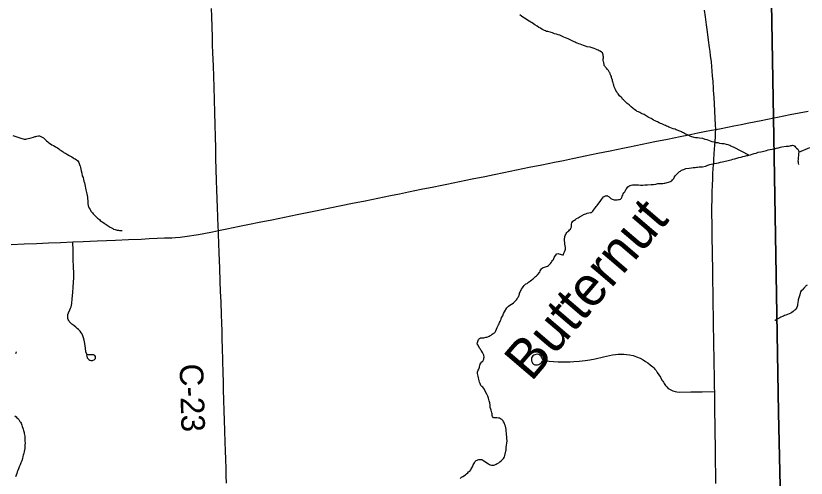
# Model space of a CAD drawing. Extents: x 103424 to 290657, y 38711 to 110967.
# Drawn here: x 139139 to 149253, y 78949 to 84863 of the extents above; entities that cross this region are included whole.
import ezdxf

# ---------------------------------------------------------------- set-up
doc = ezdxf.new("R2010")
doc.units = 0
for name, color, linetype in [('GM_X_Corporation', 7, 'Continuous'), ('GM_X_County_Road', 7, 'Continuous'), ('GM_X_County_Road_Text', 7, 'Continuous'), ('GM_X_Minor_River', 7, 'Continuous'), ('GM_X_Minor_River_Text', 7, 'Continuous'), ('GM_X_State_Route', 7, 'Continuous'), ('GM_X_Township_Road', 7, 'Continuous'), ('GM_X_US_Route', 7, 'Continuous'), ('SC_Scratch1', 7, 'Continuous')]:
    doc.layers.add(name, color=color, linetype=linetype)

msp = doc.modelspace()

# ---------------------------------------------------------------- linework, layer by layer
at = {"layer": 'GM_X_Corporation'}
for points in [[(151578, 71708), (149074, 71652), (149050, 72896), (149034, 73733), (149034, 73737), (149016, 74683), (148899, 79790), (148833, 83560), (148595, 97227), (148594, 97295), (158050, 97608)], [(148595, 97227), (148833, 83560), (148899, 79790), (149016, 74683), (149034, 73737), (149034, 73733), (149050, 72896), (149074, 71652), (148227, 71628), (148226, 71628), (142009, 71451), (141995, 71451), (137954, 71291)]]:
    msp.add_lwpolyline(points, dxfattribs=at)
at = {"layer": 'GM_X_County_Road'}
for points in [[(141731, 82115), (141728, 82158), (141723, 82294), (141719, 82407), (141715, 82521), (141712, 82639), (141708, 82757), (141704, 82896), (141700, 83036), (141697, 83176), (141693, 83316), (141689, 83470), (141684, 83624), (141680, 83788), (141676, 83952), (141672, 84088), (141667, 84224), (141662, 84389), (141658, 84490), (141655, 84591), (141652, 84723), (141648, 84855), (141645, 84957)], [(141834, 78887), (141831, 78982), (141829, 79077), (141825, 79190), (141822, 79302), (141818, 79407), (141813, 79559), (141810, 79685), (141807, 79811), (141803, 79945), (141798, 80079), (141795, 80186), (141792, 80293), (141788, 80456), (141785, 80618), (141781, 80724), (141778, 80830), (141775, 80935), (141772, 81040), (141765, 81205), (141760, 81337), (141755, 81469), (141749, 81634), (141746, 81733), (141742, 81832), (141738, 81951), (141733, 82071), (141731, 82115)]]:
    msp.add_lwpolyline(points, dxfattribs=at)
at = {"layer": 'GM_X_Minor_River'}
for points in [[(146766, 84059), (146764, 84071), (146760, 84087), (146753, 84099), (146747, 84117), (146745, 84127), (146738, 84137), (146734, 84147), (146724, 84163), (146712, 84177), (146697, 84193), (146687, 84205), (146679, 84215), (146670, 84229), (146668, 84243), (146666, 84253), (146662, 84265), (146659, 84275), (146655, 84289), (146655, 84313), (146658, 84325), (146658, 84337), (146656, 84352), (146654, 84362), (146649, 84378), (146645, 84390), (146635, 84398), (146617, 84409), (146604, 84415), (146592, 84423), (146578, 84429), (146560, 84437), (146539, 84444), (146515, 84452), (146487, 84460), (146452, 84467), (146428, 84475), (146405, 84482), (146383, 84490), (146363, 84498), (146342, 84504), (146324, 84511), (146310, 84519), (146296, 84525), (146283, 84531), (146267, 84537), (146249, 84548), (146224, 84558), (146206, 84568), (146188, 84575), (146172, 84583), (146153, 84591), (146137, 84599), (146119, 84607), (146100, 84614), (146080, 84620), (146058, 84628), (146033, 84633), (146005, 84643), (145946, 84660), (145930, 84664), (145916, 84670), (145904, 84675), (145889, 84683), (145871, 84691), (145853, 84703), (145832, 84715), (145810, 84732), (145783, 84746), (145765, 84760), (145748, 84772), (145730, 84783), (145710, 84795), (145689, 84807), (145669, 84821), (145648, 84834), (145628, 84846), (145610, 84860), (145589, 84876)], [(148521, 83080), (148332, 83178), (148323, 83184), (148309, 83189), (148291, 83197), (148275, 83203), (148256, 83211), (148234, 83216), (148204, 83224), (148175, 83227), (148147, 83231), (148125, 83237), (148102, 83240), (148078, 83246), (148052, 83251), (148029, 83259), (148009, 83267), (147987, 83275), (147960, 83282), (147930, 83292), (147890, 83297), (147861, 83301), (147837, 83304), (147821, 83308), (147805, 83312), (147790, 83315), (147778, 83321), (147762, 83329), (147744, 83335), (147725, 83343), (147709, 83350), (147695, 83358), (147683, 83364), (147670, 83372), (147658, 83380), (147648, 83384), (147638, 83387), (147603, 83399), (147591, 83405), (147575, 83411), (147552, 83418), (147528, 83426), (147510, 83434), (147496, 83439), (147481, 83445), (147467, 83453), (147453, 83459), (147439, 83465), (147422, 83472), (147404, 83480), (147388, 83486), (147371, 83494), (147351, 83505), (147337, 83513), (147319, 83521), (147300, 83529), (147284, 83539), (147268, 83548), (147249, 83558), (147233, 83566), (147217, 83576), (147204, 83582), (147192, 83590), (147178, 83601), (147154, 83609), (147137, 83617), (147123, 83627), (147107, 83634), (147092, 83640), (147082, 83646), (147072, 83652), (147056, 83664), (147043, 83672), (147033, 83682), (147015, 83697), (147002, 83711), (146988, 83723), (146974, 83733), (146963, 83743), (146953, 83751), (146937, 83767), (146927, 83777), (146914, 83789), (146902, 83798), (146894, 83812), (146865, 83840), (146855, 83852), (146846, 83864), (146840, 83874), (146830, 83890), (146819, 83908), (146813, 83920), (146803, 83938), (146796, 83956), (146792, 83974), (146788, 83990), (146783, 84004), (146779, 84016), (146775, 84028), (146773, 84039), (146766, 84059)], [(139101, 83333), (139217, 83293), (139233, 83289), (139245, 83287), (139268, 83287), (139282, 83290), (139298, 83294), (139318, 83298), (139336, 83301), (139364, 83311), (139376, 83314), (139386, 83318), (139396, 83320), (139410, 83324), (139428, 83327), (139442, 83329), (139485, 83308), (139495, 83300), (139506, 83290), (139520, 83278), (139532, 83264), (139547, 83252), (139563, 83238), (139581, 83224), (139602, 83213), (139620, 83205), (139641, 83193), (139657, 83183), (139673, 83172), (139690, 83160), (139704, 83150), (139718, 83140), (139732, 83130), (139745, 83122), (139759, 83112), (139773, 83105), (139788, 83097), (139802, 83087), (139822, 83077), (139839, 83067), (139857, 83058), (139873, 83048), (139887, 83038), (139898, 83032), (139914, 83020), (139930, 83010), (139939, 82999), (139947, 82985), (139949, 82974), (139953, 82962), (139958, 82950), (139962, 82938), (139966, 82922), (139971, 82902), (139975, 82880), (139982, 82852), (139990, 82818), (139999, 82794), (140005, 82771), (140010, 82749), (140016, 82727), (140021, 82707), (140034, 82639), (140038, 82621), (140045, 82602), (140049, 82586), (140053, 82564), (140056, 82544), (140058, 82522), (140059, 82500), (140059, 82479), (140061, 82465), (140061, 82455), (140064, 82445), (140066, 82433), (140070, 82423), (140074, 82413), (140078, 82401), (140089, 82385), (140095, 82375), (140101, 82365), (140112, 82353), (140120, 82341), (140130, 82329), (140143, 82317), (140155, 82305), (140169, 82290), (140186, 82274), (140208, 82258), (140220, 82246), (140237, 82234), (140251, 82222), (140268, 82211), (140282, 82201), (140294, 82193), (140306, 82185), (140319, 82177), (140335, 82167), (140345, 82159), (140357, 82154), (140370, 82148)], [(147824, 82922), (147834, 82924), (147848, 82925), (147864, 82927), (147884, 82929), (147908, 82930), (147926, 82932), (147967, 82941), (147979, 82945), (147993, 82951), (148007, 82956), (148021, 82960), (148039, 82964), (148057, 82969), (148081, 82973), (148107, 82980), (148133, 82984), (148157, 82991), (148181, 82995), (148200, 82998), (148218, 83002), (148236, 83006), (148254, 83011), (148274, 83015), (148294, 83021), (148316, 83028), (148342, 83034), (148368, 83043), (148390, 83049), (148420, 83056), (148443, 83063), (148463, 83067), (148481, 83071), (148495, 83074), (148507, 83076), (148521, 83080), (148541, 83086), (148563, 83093), (148587, 83101), (148615, 83108), (148641, 83117), (148672, 83123), (148694, 83128), (148712, 83132), (148728, 83136), (148746, 83141), (148768, 83147), (148792, 83152), (148816, 83158), (148840, 83163), (148860, 83165), (148874, 83169), (148891, 83172), (148901, 83176), (148911, 83178), (148923, 83182), (148943, 83187), (148999, 83194), (149009, 83196), (149025, 83196), (149047, 83201), (149057, 83203), (149070, 83205), (149080, 83207), (149096, 83204), (149106, 83194), (149118, 83182), (149131, 83168), (149147, 83156), (149153, 83140), (149158, 83128), (149158, 83118), (149156, 83102), (149156, 83089), (149155, 83077), (149151, 83049), (149149, 83027), (149148, 83009), (149150, 82994), (149152, 82980), (149152, 82980), (149152, 82978), (149157, 82962)], [(149158, 83118), (149298, 83177)], [(146254, 82215), (146268, 82236), (146280, 82244), (146290, 82250), (146302, 82258), (146316, 82269), (146334, 82277), (146348, 82287), (146362, 82296), (146376, 82304), (146394, 82315), (146404, 82321), (146416, 82327), (146432, 82331), (146452, 82338), (146470, 82342), (146492, 82347), (146504, 82349), (146514, 82355), (146522, 82365), (146532, 82378), (146544, 82394), (146556, 82410), (146567, 82425), (146577, 82437), (146585, 82449), (146615, 82488), (146625, 82501), (146632, 82513), (146646, 82529), (146660, 82546), (146670, 82552), (146686, 82560), (146696, 82562), (146706, 82563), (146716, 82557), (146731, 82547), (146741, 82537), (146755, 82527), (146769, 82519), (146784, 82513), (146798, 82510), (146812, 82508), (146836, 82510), (146850, 82513), (146866, 82515), (146876, 82519), (146888, 82530), (146894, 82540), (146900, 82554), (146906, 82568), (146912, 82584), (146921, 82599), (146931, 82611), (146941, 82627), (146947, 82640), (146953, 82650), (146961, 82662), (146972, 82676), (146982, 82683), (147000, 82693), (147014, 82697), (147029, 82700), (147045, 82700), (147107, 82699), (147134, 82698), (147162, 82698), (147190, 82699), (147222, 82699), (147269, 82704), (147301, 82707), (147329, 82711), (147353, 82716), (147375, 82718), (147391, 82718), (147406, 82719), (147420, 82719), (147434, 82721), (147446, 82723), (147460, 82726), (147474, 82730), (147492, 82734), (147504, 82739), (147516, 82743), (147532, 82751), (147542, 82763), (147558, 82782), (147566, 82794), (147577, 82815), (147601, 82841), (147619, 82858), (147633, 82870), (147643, 82874), (147659, 82887), (147669, 82891), (147689, 82899), (147715, 82908), (147757, 82915), (147785, 82919), (147807, 82922), (147824, 82922)], [(140370, 82148), (140380, 82142), (140390, 82136), (140410, 82128), (140422, 82124), (140437, 82123), (140451, 82119), (140467, 82117), (140477, 82117), (140499, 82118), (140499, 82118), (140501, 82118)], [(145309, 80895), (145317, 80911), (145323, 80924), (145329, 80940), (145337, 80954), (145342, 80966), (145348, 80981), (145356, 81005), (145370, 81027), (145381, 81054), (145393, 81078), (145424, 81129), (145434, 81140), (145444, 81150), (145460, 81160), (145482, 81175), (145492, 81181), (145508, 81192), (145522, 81204), (145538, 81220), (145546, 81231), (145555, 81243), (145565, 81259), (145573, 81270), (145577, 81280), (145581, 81290), (145585, 81302), (145586, 81314), (145592, 81328), (145598, 81343), (145604, 81353), (145612, 81367), (145624, 81384), (145631, 81398), (145643, 81412), (145657, 81425), (145667, 81433), (145681, 81441), (145699, 81456), (145711, 81466), (145727, 81474), (145741, 81485), (145751, 81493), (145763, 81501), (145779, 81518), (145788, 81528), (145802, 81538), (145814, 81551), (145844, 81585), (145850, 81602), (145856, 81614), (145865, 81628), (145875, 81637), (145887, 81643), (145903, 81649), (145917, 81653), (145931, 81658), (145941, 81662), (145955, 81670), (145965, 81677), (145981, 81693), (145993, 81711), (145997, 81722), (146007, 81734), (146021, 81746), (146026, 81760), (146030, 81771), (146036, 81785), (146046, 81799), (146062, 81818), (146078, 81822), (146090, 81818), (146104, 81814), (146118, 81811), (146133, 81807), (146147, 81807), (146154, 81825), (146162, 81842), (146168, 81864), (146172, 81878), (146173, 81890), (146173, 81900), (146166, 81943), (146164, 81961), (146162, 81987), (146161, 82011), (146163, 82030), (146165, 82042), (146168, 82054), (146176, 82066), (146182, 82080), (146192, 82093), (146202, 82105), (146214, 82113), (146224, 82124), (146236, 82136), (146241, 82146), (146251, 82162), (146251, 82183), (146251, 82197), (146254, 82215)], [(149265, 81419), (149249, 81410), (149245, 81400), (149223, 81378), (149202, 81355), (149190, 81347), (149182, 81334), (149176, 81310), (149169, 81282), (149151, 81231), (149150, 81219), (149148, 81202), (149146, 81190)], [(149146, 81190), (149142, 81174), (149141, 81158), (149137, 81146), (149133, 81131), (149127, 81119), (149121, 81107), (149109, 81099), (149099, 81093), (149087, 81080), (149071, 81070), (149058, 81061), (149035, 81051), (149013, 81042), (148995, 81034), (148977, 81028), (148961, 81021), (148951, 81017), (148931, 81009), (148915, 81000), (148899, 80990), (148881, 80982), (148869, 80975), (148855, 80965), (148851, 80965)], [(145411, 79293), (145413, 79307), (145412, 79323), (145416, 79343), (145420, 79370), (145423, 79398), (145425, 79426), (145424, 79455), (145422, 79481), (145419, 79503), (145417, 79525), (145416, 79550), (145412, 79572), (145410, 79592), (145405, 79614), (145399, 79632), (145392, 79652), (145382, 79670), (145374, 79684), (145357, 79700), (145343, 79710), (145329, 79716), (145314, 79715), (145296, 79719), (145284, 79719), (145272, 79721), (145260, 79722), (145250, 79722), (145241, 79736), (145237, 79752), (145235, 79771), (145230, 79787), (145226, 79801), (145222, 79817), (145218, 79833), (145211, 79855), (145209, 79883), (145204, 79911), (145198, 79938), (145189, 79972), (145180, 79998), (145168, 80024), (145128, 80098), (145114, 80114), (145103, 80122), (145089, 80136), (145081, 80160), (145074, 80176), (145070, 80194), (145063, 80214), (145059, 80234), (145055, 80252), (145050, 80270), (145048, 80286), (145046, 80296), (145048, 80311), (145057, 80329), (145065, 80345), (145071, 80370), (145076, 80394), (145082, 80408), (145090, 80418), (145104, 80437), (145114, 80445), (145124, 80461), (145127, 80472), (145129, 80482), (145131, 80496), (145129, 80522), (145120, 80538), (145110, 80558), (145099, 80576), (145091, 80588), (145085, 80598), (145074, 80612), (145054, 80650), (145045, 80666), (145049, 80684), (145053, 80699), (145060, 80723), (145072, 80737), (145084, 80742), (145096, 80742), (145106, 80742), (145118, 80744), (145129, 80744), (145139, 80747), (145153, 80751), (145167, 80753), (145181, 80759), (145195, 80764), (145211, 80772), (145223, 80778), (145233, 80789), (145249, 80801), (145263, 80807), (145275, 80816), (145282, 80834), (145290, 80854), (145300, 80875), (145309, 80895)], [(139145, 80566), (139145, 80562), (139139, 80554), (139135, 80538)], [(139125, 79748), (139142, 79732), (139154, 79722), (139164, 79714), (139176, 79700), (139183, 79690), (139191, 79676), (139199, 79664), (139206, 79652), (139210, 79640), (139214, 79626), (139220, 79608), (139229, 79590), (139233, 79574), (139237, 79560), (139242, 79546), (139244, 79534), (139246, 79520), (139251, 79503), (139253, 79485), (139255, 79463), (139256, 79441), (139256, 79421), (139257, 79396), (139255, 79376), (139255, 79358), (139253, 79344), (139254, 79330), (139248, 79289), (139243, 79265), (139237, 79255), (139233, 79245), (139229, 79226), (139224, 79202), (139214, 79173), (139203, 79147), (139193, 79121), (139181, 79094), (139172, 79070), (139164, 79049), (139158, 79029), (139151, 79007), (139145, 78986), (139137, 78968)], [(144824, 78945), (144844, 78961), (144860, 78970), (144894, 78991), (144906, 79003), (144923, 79019), (144933, 79030), (144947, 79038), (144961, 79057), (144967, 79069), (144975, 79083), (144983, 79095), (144986, 79105), (144992, 79120), (145000, 79134), (145008, 79146), (145014, 79158), (145030, 79175), (145042, 79181), (145052, 79185), (145064, 79188), (145082, 79190), (145094, 79188), (145104, 79186), (145116, 79181), (145128, 79173), (145151, 79159), (145167, 79145), (145186, 79133), (145200, 79123), (145210, 79120), (145228, 79114), (145240, 79114), (145255, 79116), (145271, 79121), (145285, 79127), (145301, 79135), (145319, 79146), (145335, 79160), (145354, 79175), (145368, 79187), (145380, 79199), (145388, 79212), (145394, 79224), (145398, 79238), (145407, 79277), (145411, 79293)]]:
    msp.add_lwpolyline(points, dxfattribs=at)
at = {"layer": 'GM_X_State_Route'}
for points in [[(148097, 83410), (148095, 83467), (148090, 83551), (148085, 83648), (148080, 83735), (148075, 83819), (148069, 83912), (148068, 83936), (148062, 84022), (148056, 84097), (148046, 84216), (148040, 84272), (148029, 84357), (148023, 84406), (148016, 84458), (148004, 84551), (147990, 84659), (147978, 84746), (147965, 84849), (147954, 84933)], [(148097, 83410), (148095, 83467), (148090, 83551), (148085, 83648), (148080, 83735), (148075, 83819), (148069, 83912), (148068, 83936), (148062, 84022), (148056, 84097), (148046, 84216), (148040, 84272), (148029, 84357), (148023, 84406), (148016, 84458), (148004, 84551), (147990, 84659), (147978, 84746), (147965, 84849), (147954, 84933)], [(148064, 82896), (148064, 82907), (148068, 82955), (148070, 82989), (148072, 83027), (148077, 83095), (148081, 83163), (148084, 83202), (148088, 83260), (148091, 83313), (148095, 83372), (148097, 83410)], [(148064, 82896), (148064, 82907), (148068, 82955), (148070, 82989), (148072, 83027), (148077, 83095), (148081, 83163), (148084, 83202), (148088, 83260), (148091, 83313), (148095, 83372), (148097, 83410)], [(148099, 78883), (148098, 78956), (148096, 79039), (148094, 79122), (148093, 79235), (148092, 79320), (148092, 79402), (148090, 79484), (148088, 79573), (148087, 79681), (148086, 79748), (148086, 79870), (148085, 79934), (148084, 80012), (148083, 80057), (148082, 80106), (148081, 80164), (148080, 80212), (148079, 80289), (148077, 80380), (148076, 80458), (148075, 80527), (148073, 80610), (148072, 80682), (148071, 80767), (148069, 80850), (148068, 80922), (148067, 81001), (148066, 81066), (148065, 81119), (148064, 81172), (148063, 81235), (148062, 81298), (148062, 81357), (148060, 81435), (148060, 81495), (148058, 81567), (148057, 81663), (148056, 81761), (148055, 81825), (148054, 81897), (148052, 81977), (148051, 82065), (148050, 82131), (148049, 82222), (148048, 82303), (148047, 82358), (148048, 82409), (148050, 82519), (148052, 82608), (148054, 82701), (148057, 82773), (148060, 82853), (148064, 82896)], [(148099, 78883), (148098, 78956), (148096, 79039), (148094, 79122), (148093, 79235), (148092, 79320), (148092, 79402), (148090, 79484), (148088, 79573), (148087, 79681), (148086, 79748), (148086, 79870), (148085, 79934), (148084, 80012), (148083, 80057), (148082, 80106), (148081, 80164), (148080, 80212), (148079, 80289), (148077, 80380), (148076, 80458), (148075, 80527), (148073, 80610), (148072, 80682), (148071, 80767), (148069, 80850), (148068, 80922), (148067, 81001), (148066, 81066), (148065, 81119), (148064, 81172), (148063, 81235), (148062, 81298), (148062, 81357), (148060, 81435), (148060, 81495), (148058, 81567), (148057, 81663), (148056, 81761), (148055, 81825), (148054, 81897), (148052, 81977), (148051, 82065), (148050, 82131), (148049, 82222), (148048, 82303), (148047, 82358), (148048, 82409), (148050, 82519), (148052, 82608), (148054, 82701), (148057, 82773), (148060, 82853), (148064, 82896)]]:
    msp.add_lwpolyline(points, dxfattribs=at)
at = {"layer": 'GM_X_Township_Road'}
for points in [[(140045, 80531), (140048, 80504), (140050, 80495), (140053, 80488), (140060, 80478), (140073, 80466), (140085, 80459), (140101, 80456), (140119, 80455), (140131, 80458), (140141, 80463), (140148, 80467), (140157, 80481), (140160, 80492), (140158, 80507), (140149, 80519), (140141, 80523), (140133, 80525), (140117, 80527), (140092, 80527), (140063, 80528), (140058, 80529), (140052, 80532), (140047, 80537), (140044, 80543), (140037, 80563), (140030, 80612), (140021, 80672), (140012, 80715), (140005, 80745), (139995, 80771), (139984, 80798), (139976, 80809), (139962, 80829), (139943, 80849), (139926, 80865), (139908, 80879), (139883, 80900), (139858, 80919), (139846, 80929), (139835, 80939), (139822, 80953), (139816, 80964), (139810, 80979), (139806, 80993), (139803, 81010), (139803, 81025), (139806, 81042), (139813, 81062), (139832, 81102), (139840, 81122), (139846, 81141), (139851, 81161), (139856, 81184), (139861, 81241), (139868, 81326), (139874, 81392), (139878, 81456), (139880, 81513), (139881, 81566), (139878, 81655), (139875, 81743), (139871, 81857), (139868, 81971)], [(145889, 80452), (145874, 80482), (145868, 80496), (145861, 80508), (145852, 80516), (145844, 80523), (145831, 80530), (145811, 80535), (145780, 80528), (145768, 80522), (145757, 80514), (145747, 80501), (145739, 80487), (145737, 80467), (145739, 80450), (145745, 80432), (145751, 80419), (145765, 80407), (145783, 80400), (145800, 80397), (145815, 80398), (145830, 80401), (145846, 80412), (145857, 80421), (145870, 80434), (145878, 80444), (145898, 80451), (145924, 80449), (145965, 80445), (146019, 80443), (146079, 80439), (146139, 80436), (146231, 80437), (146278, 80440), (146350, 80444), (146423, 80453), (146484, 80464), (146554, 80477), (146659, 80501), (146738, 80519), (146774, 80527), (146812, 80532), (146846, 80535), (146878, 80535), (146920, 80534), (146952, 80532), (146991, 80528), (147038, 80517), (147084, 80501), (147129, 80482), (147167, 80462), (147198, 80443), (147227, 80424), (147258, 80400), (147289, 80374), (147303, 80359), (147318, 80342), (147332, 80325), (147348, 80302), (147369, 80270), (147387, 80240), (147408, 80204), (147417, 80191), (147426, 80176), (147436, 80161), (147451, 80135), (147469, 80117), (147489, 80097), (147504, 80088), (147522, 80077), (147547, 80068), (147575, 80059), (147597, 80054), (147629, 80051), (147776, 80053), (147924, 80054), (148083, 80057)]]:
    msp.add_lwpolyline(points, dxfattribs=at)
at = {"layer": 'GM_X_US_Route'}
for points in [[(148097, 83410), (148165, 83423), (148327, 83454), (148423, 83473), (148519, 83492), (148679, 83525), (148838, 83558)], [(148838, 83558), (148886, 83566), (149047, 83599), (149163, 83622), (149278, 83645)], [(146283, 83042), (146424, 83071), (146585, 83104), (146746, 83136), (146906, 83169), (146992, 83187), (147154, 83220), (147316, 83253), (147477, 83286), (147639, 83319), (147753, 83342), (147867, 83365), (147954, 83382), (148041, 83399), (148097, 83410)], [(139081, 81937), (139246, 81945), (139403, 81952), (139559, 81959), (139713, 81965), (139868, 81971), (140000, 81976), (140091, 81980), (140182, 81984), (140299, 81989), (140415, 81994), (140580, 82001), (140745, 82008), (140846, 82013), (140947, 82017), (141042, 82021), (141137, 82025), (141184, 82028), (141242, 82033), (141301, 82040), (141360, 82047), (141417, 82056), (141477, 82066), (141544, 82079), (141657, 82101), (141731, 82115), (141840, 82138), (142002, 82171), (142128, 82197), (142253, 82222), (142415, 82255), (142577, 82288), (142739, 82321), (142867, 82347), (142994, 82373), (143156, 82405), (143302, 82435), (143448, 82465), (143610, 82498), (143771, 82531), (143933, 82564), (144048, 82587), (144164, 82611), (144325, 82644), (144487, 82676), (144570, 82693), (144653, 82710), (144815, 82743), (144977, 82776), (145139, 82809), (145261, 82834), (145384, 82859), (145545, 82892), (145707, 82925), (145869, 82958), (146031, 82991), (146146, 83014), (146262, 83038), (146283, 83042)]]:
    msp.add_lwpolyline(points, dxfattribs=at)
at = {"layer": 'SC_Scratch1'}
for points in [[(146283, 83042), (146424, 83071), (146585, 83104), (146746, 83136), (146906, 83169), (146992, 83187), (147154, 83220), (147316, 83253), (147477, 83286), (147639, 83319), (147753, 83342), (147867, 83365), (147954, 83382), (148041, 83399), (148097, 83410)], [(139081, 81937), (139246, 81945), (139403, 81952), (139559, 81959), (139713, 81965), (139868, 81971), (140000, 81976), (140091, 81980), (140182, 81984), (140299, 81989), (140415, 81994), (140580, 82001), (140745, 82008), (140846, 82013), (140947, 82017), (141042, 82021), (141137, 82025), (141184, 82028), (141242, 82033), (141301, 82040), (141360, 82047), (141417, 82056), (141477, 82066), (141544, 82079), (141657, 82101), (141731, 82115), (141840, 82138), (142002, 82171), (142128, 82197), (142253, 82222), (142415, 82255), (142577, 82288), (142739, 82321), (142867, 82347), (142994, 82373), (143156, 82405), (143302, 82435), (143448, 82465), (143610, 82498), (143771, 82531), (143933, 82564), (144048, 82587), (144164, 82611), (144325, 82644), (144487, 82676), (144570, 82693), (144653, 82710), (144815, 82743), (144977, 82776), (145139, 82809), (145261, 82834), (145384, 82859), (145545, 82892), (145707, 82925), (145869, 82958), (146031, 82991), (146146, 83014), (146262, 83038), (146283, 83042)]]:
    msp.add_lwpolyline(points, dxfattribs=at)

# ---------------------------------------------------------------- texts
at = {"layer": 'GM_X_County_Road_Text'}
msp.add_text('C-23', height=301.9, rotation=271.7153, dxfattribs=at).set_placement((141234, 80410))
at = {"layer": 'GM_X_Minor_River_Text'}
msp.add_text('Butternut', height=503.5, rotation=49.4982, dxfattribs=at).set_placement((145735, 80172))

doc.saveas('drawing.dxf')
